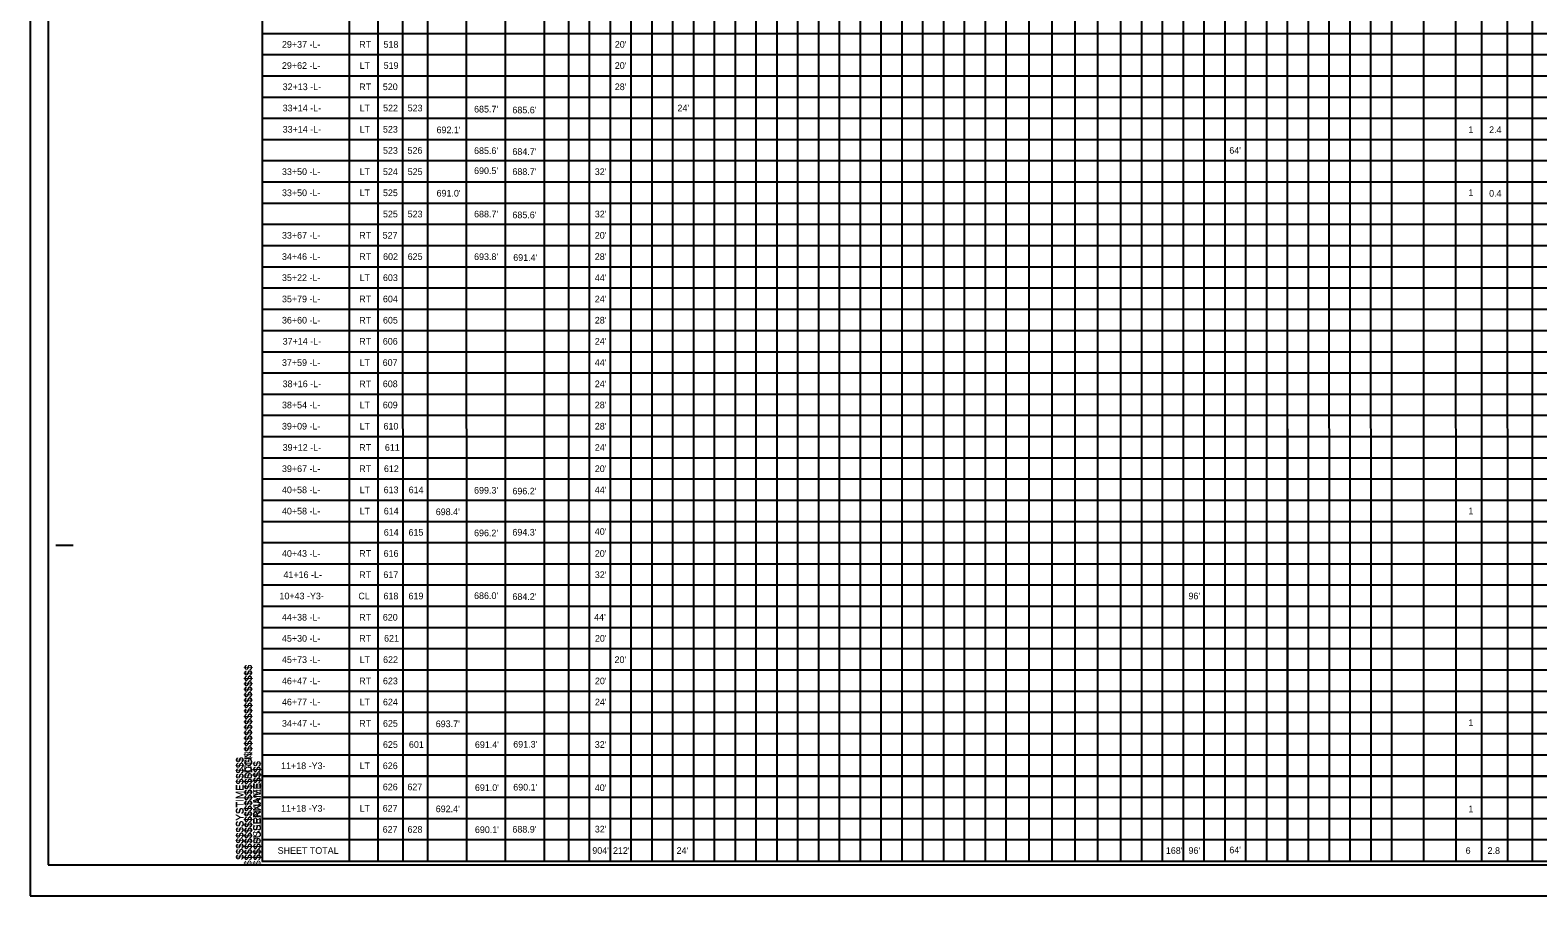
# Model space of a CAD drawing. Extents: x 1912419 to 1914138, y 231793 to 234289.
# Drawn here: x 1912419 to 1913505, y 232988 to 233611 of the extents above; entities that cross this region are included whole.
import ezdxf

# ---------------------------------------------------------------- set-up
doc = ezdxf.new("R2010")
doc.units = 0
for name, color, linetype in [('Sheet Cutting Line CELL', 7, 'Continuous'), ('Sheet Pipe Summary CELL', 7, 'Continuous'), ('Sheet Pipe Summary Grid CELL', 7, 'Continuous'), ('Sheet Plot Border Inside CELL', 7, 'Continuous'), ('Sheet Plot Border Outside CELL', 7, 'Continuous'), ('Sheet Summary Combination CELL', 7, 'Continuous')]:
    doc.layers.add(name, color=color, linetype=linetype)

msp = doc.modelspace()

# ---------------------------------------------------------------- linework, layer by layer
at = {"layer": 'Sheet Cutting Line CELL'}
for p, q in [((1912419.4, 234087.8), (1912419.4, 232987.8)), ((1912419.4, 232987.8), (1914103.4, 232987.8)), ((1912419.4, 232987.8), (1914103.4, 232987.8))]:
    msp.add_line(p, q, dxfattribs=at)
at = {"layer": 'Sheet Pipe Summary CELL'}
for p, q in [((1912437.9, 233240.3), (1912450.4, 233240.3)), ((1912437.9, 233240.3), (1912450.4, 233240.3)), ((1912586.4, 233012.8), (1912586.4, 233012.8))]:
    msp.add_line(p, q, dxfattribs=at)
msp.add_lwpolyline([(1914086.4, 234062.8), (1912586.4, 234062.8), (1912586.4, 233012.8), (1914086.4, 233012.8)], close=True, dxfattribs=at)
at = {"layer": 'Sheet Pipe Summary Grid CELL'}
for p, q in [((1912649.4, 233012.8), (1912649.4, 233966.6)), ((1912670, 233012.8), (1912669.9, 233966.6)), ((1912705.7, 233012.8), (1912705.7, 233966.6)), ((1912733.7, 233012.8), (1912733.6, 233966.6)), ((1912761.7, 233012.8), (1912761.6, 233966.6)), ((1912789.6, 233012.8), (1912789.6, 233966.6)), ((1912807.1, 233012.8), (1912807.1, 233966.6)), ((1912987.1, 233012.8), (1912987.1, 233966.6)), ((1913092.1, 233012.8), (1913092.1, 233966.6)), ((1913204.7, 233012.9), (1913204.6, 233966.7)), ((1913324.7, 233012.9), (1913324.6, 233966.7)), ((1913339.7, 233012.9), (1913339.6, 233966.7)), ((1913354.7, 233012.9), (1913354.6, 233966.7)), ((1913369.7, 233012.9), (1913369.6, 233966.7)), ((1913384.7, 233012.9), (1913384.6, 233966.7)), ((1913399.7, 233012.9), (1913399.6, 233966.7)), ((1913399.6, 233012.9), (1913399.6, 233966.7)), ((1913445.9, 233012.9), (1913445.8, 233966.7)), ((1913500.9, 233012.9), (1913500.8, 233966.7)), ((1913500.9, 233012.9), (1913500.8, 233966.7)), ((1913464.5, 233012.9), (1913464.4, 233876)), ((1912822.1, 233012.8), (1912822.1, 233858.8)), ((1912837.1, 233012.8), (1912837.1, 233858.8)), ((1912852.1, 233012.8), (1912852.1, 233858.8)), ((1912867.1, 233012.8), (1912867.1, 233858.8)), ((1912882.1, 233012.8), (1912882.1, 233858.8)), ((1912897.1, 233012.8), (1912897.1, 233858.8)), ((1912912.1, 233012.8), (1912912.1, 233858.8)), ((1912927.1, 233012.8), (1912927.1, 233858.8)), ((1912942.1, 233012.8), (1912942.1, 233858.8)), ((1912957.1, 233012.8), (1912957.1, 233858.8)), ((1912972.1, 233012.8), (1912972.1, 233858.8)), ((1913002.1, 233012.8), (1913002.1, 233858.8)), ((1913017.1, 233012.8), (1913017.1, 233858.8)), ((1913032.1, 233012.8), (1913032.1, 233858.8)), ((1913047.1, 233012.8), (1913047.1, 233858.8)), ((1913062.1, 233012.8), (1913062.1, 233858.8)), ((1913077.1, 233012.8), (1913077.1, 233858.8)), ((1913092.1, 233012.8), (1913092.1, 233858.8)), ((1913107.1, 233012.8), (1913107.1, 233858.8)), ((1913122.1, 233012.8), (1913122.1, 233858.8)), ((1913138.6, 233012.8), (1913138.6, 233858.8)), ((1913155.1, 233012.8), (1913155.1, 233858.8)), ((1913171.6, 233012.8), (1913171.6, 233858.8)), ((1913188.1, 233012.8), (1913188.1, 233858.8)), ((1913204.6, 233012.8), (1913204.6, 233858.8)), ((1913219.6, 233012.8), (1913219.6, 233858.8)), ((1913234.6, 233012.8), (1913234.6, 233858.8)), ((1913249.6, 233012.8), (1913249.6, 233858.8)), ((1913264.6, 233012.8), (1913264.6, 233858.8)), ((1913279.6, 233012.8), (1913279.6, 233858.8)), ((1913294.6, 233012.8), (1913294.6, 233858.8)), ((1913309.6, 233012.8), (1913309.6, 233858.8)), ((1913324.6, 233012.8), (1913324.6, 233858.8)), ((1913483.1, 233012.9), (1913483, 233852.8)), ((1912687.9, 233012.8), (1912687.8, 233833.3)), ((1912987.1, 233012.8), (1912987.1, 233833.4)), ((1913422.8, 233012.9), (1913422.7, 233833.5)), ((1914086.4, 233608.3), (1912586.4, 233608.3)), ((1914086.4, 233593), (1912586.4, 233593)), ((1914086.4, 233577.8), (1912586.4, 233577.8)), ((1914086.4, 233562.5), (1912586.4, 233562.5)), ((1914086.4, 233547.2), (1912586.4, 233547.2)), ((1914086.4, 233531.9), (1912586.4, 233531.9)), ((1914086.4, 233516.7), (1912586.4, 233516.7)), ((1914086.4, 233501.4), (1912586.4, 233501.4)), ((1914086.4, 233486.1), (1912586.4, 233486.1)), ((1914086.4, 233470.9), (1912586.4, 233470.9)), ((1914086.4, 233455.6), (1912586.4, 233455.6)), ((1914086.4, 233440.3), (1912586.4, 233440.3)), ((1914086.4, 233425.1), (1912586.4, 233425.1)), ((1914086.4, 233409.8), (1912586.4, 233409.8)), ((1914086.4, 233394.5), (1912586.4, 233394.5)), ((1914086.4, 233379.2), (1912586.4, 233379.2)), ((1914086.4, 233364), (1912586.4, 233364)), ((1914086.4, 233348.7), (1912586.4, 233348.7)), ((1914086.4, 233333.4), (1912586.4, 233333.4)), ((1914086.4, 233318.2), (1912586.4, 233318.2)), ((1914086.4, 233302.9), (1912586.4, 233302.9)), ((1914086.4, 233287.6), (1912586.4, 233287.6)), ((1914086.4, 233272.4), (1912586.4, 233272.4)), ((1914086.4, 233257.1), (1912586.4, 233257.1)), ((1914086.4, 233241.8), (1912586.4, 233241.8)), ((1914086.4, 233226.5), (1912586.4, 233226.5)), ((1914086.4, 233211.3), (1912586.4, 233211.3)), ((1914086.4, 233196), (1912586.4, 233196)), ((1914086.4, 233180.7), (1912586.4, 233180.7)), ((1914086.4, 233165.5), (1912586.4, 233165.5)), ((1914086.4, 233150.2), (1912586.4, 233150.2)), ((1914086.4, 233134.9), (1912586.4, 233134.9)), ((1914086.4, 233119.7), (1912586.4, 233119.7)), ((1914086.4, 233104.4), (1912586.4, 233104.4)), ((1914086.4, 233089.1), (1912586.4, 233089.1)), ((1914086.4, 233073.9), (1912586.4, 233073.9)), ((1914086.4, 233073.8), (1912586.4, 233073.8)), ((1914086.4, 233058.6), (1912586.4, 233058.6)), ((1914086.4, 233043.3), (1912586.4, 233043.3)), ((1914086.4, 233028.1), (1912586.4, 233028.1))]:
    msp.add_line(p, q, dxfattribs=at)
at = {"layer": 'Sheet Plot Border Inside CELL'}
msp.add_lwpolyline([(1912432.4, 233010.2), (1914098.9, 233010.2), (1914098.9, 234065.3), (1912432.4, 234065.3)], close=True, dxfattribs=at)
at = {"layer": 'Sheet Plot Border Outside CELL'}
msp.add_lwpolyline([(1912419.4, 232987.8), (1914103.4, 232987.8), (1914103.4, 234087.8), (1912419.4, 234087.8)], close=True, dxfattribs=at)

# ---------------------------------------------------------------- texts
at = {"layer": 'Sheet Pipe Summary CELL'}
for s, p in [('$$$$$$$$$$$$$$$$DGN$$$$$$$$$$$$$$$$', (1912578.8, 233013.6)), ('$$$$$$$$$$$$$$$$DGN$$$$$$$$$$$$$$$$', (1912579.3, 233013.6)), ('$$$$$$SYSTIME$$$$$', (1912572.7, 233013.8)), ('$$$$$$SYSTIME$$$$$', (1912573.2, 233013.8)), ('$$$$USERNAME$$$$', (1912585.1, 233013.7)), ('$$$$USERNAME$$$$', (1912585.6, 233013.7))]:
    msp.add_text(s, height=5.25, rotation=90, dxfattribs=at).set_placement(p)
at = {"layer": 'Sheet Summary Combination CELL'}
for s, p in [('29+37 -L-', (1912600.7, 233598.2)), ('RT', (1912656.3, 233598.2)), ('518', (1912673.8, 233598.2)), ("20'", (1912840.3, 233598.2)), ('29+62 -L-', (1912600.7, 233583)), ('LT', (1912656.6, 233583)), ('519', (1912673.9, 233583)), ("20'", (1912840.3, 233583)), ('32+13 -L-', (1912601.2, 233567.7)), ('RT', (1912656.3, 233567.7)), ('520', (1912673.3, 233567.7)), ("28'", (1912840.3, 233567.7)), ('33+14 -L-', (1912601.2, 233552.4)), ('LT', (1912656.6, 233552.4)), ('522', (1912673.5, 233552.4)), ('523', (1912691.2, 233552.4)), ("685.7'", (1912739, 233551.6)), ("685.6'", (1912766.6, 233551)), ("24'", (1912885.4, 233552.4)), ('33+14 -L-', (1912601.2, 233537.1)), ('LT', (1912656.6, 233537.1)), ('523', (1912673.4, 233537.1)), ("692.1'", (1912712, 233536.7)), ('1', (1913454.8, 233536.8)), ('2.4', (1913469.7, 233536.8)), ('523', (1912673.4, 233521.9)), ('526', (1912691.1, 233521.9)), ("685.6'", (1912739, 233521.7)), ("684.7'", (1912766.6, 233521.1)), ("64'", (1913282.7, 233521.9)), ('33+50 -L-', (1912600.7, 233506.6)), ('LT', (1912656.6, 233506.6)), ('524', (1912673.4, 233506.6)), ('525', (1912691.2, 233506.6)), ("690.5'", (1912739, 233507.3)), ("688.7'", (1912766.6, 233506.7)), ("32'", (1912825.9, 233506.6)), ('33+50 -L-', (1912600.7, 233491.4)), ('LT', (1912656.6, 233491.4)), ('525', (1912673.4, 233491.4)), ("691.0'", (1912712, 233491.1)), ('1', (1913454.8, 233491.5)), ('0.4', (1913469.7, 233491)), ('525', (1912673.4, 233476.1)), ('523', (1912691.2, 233476.1)), ("688.7'", (1912739, 233476.1)), ("685.6'", (1912766.6, 233475.5)), ("32'", (1912825.9, 233476.1)), ('33+67 -L-', (1912600.7, 233460.8)), ('RT', (1912656.3, 233460.8)), ('527', (1912673.2, 233460.8)), ("20'", (1912825.9, 233460.8)), ('34+46 -L-', (1912600.7, 233445.5)), ('RT', (1912656.3, 233445.5)), ('602', (1912673.5, 233445.5)), ('625', (1912691.2, 233445.5)), ("693.8'", (1912739, 233445.4)), ("28'", (1912825.9, 233445.5)), ("691.4'", (1912767.2, 233444.8)), ('35+22 -L-', (1912600.7, 233430.3)), ('LT', (1912656.6, 233430.3)), ('603', (1912673.4, 233430.3)), ("44'", (1912825.9, 233430.3)), ('35+79 -L-', (1912600.7, 233415)), ('RT', (1912656.3, 233415)), ('604', (1912673.4, 233415)), ("24'", (1912825.9, 233415)), ('36+60 -L-', (1912600.7, 233399.7)), ('RT', (1912656.3, 233399.7)), ('605', (1912673.4, 233399.7)), ("28'", (1912825.9, 233399.7)), ('37+14 -L-', (1912601.2, 233384.5)), ('RT', (1912656.3, 233384.5)), ('606', (1912673.3, 233384.5)), ("24'", (1912825.9, 233384.5)), ('37+59 -L-', (1912600.7, 233369.2)), ('LT', (1912656.6, 233369.2)), ('607', (1912673.2, 233369.2)), ("44'", (1912825.9, 233369.2)), ('38+16 -L-', (1912601.2, 233353.9)), ('RT', (1912656.3, 233353.9)), ('608', (1912673.3, 233353.9)), ("24'", (1912825.9, 233353.9)), ('38+54 -L-', (1912600.7, 233338.7)), ('LT', (1912656.6, 233338.7)), ('609', (1912673.3, 233338.7)), ("28'", (1912825.9, 233338.7)), ('39+09 -L-', (1912600.7, 233323.4)), ('LT', (1912656.6, 233323.4)), ('610', (1912673.8, 233323.4)), ("28'", (1912825.9, 233323.4)), ('39+12 -L-', (1912601.2, 233308.1)), ('RT', (1912656.3, 233308.1)), ('611', (1912674.8, 233308.1)), ("24'", (1912825.9, 233308.1)), ('39+67 -L-', (1912600.7, 233292.8)), ('RT', (1912656.3, 233292.8)), ('612', (1912674.1, 233292.8)), ("20'", (1912825.9, 233292.8)), ('40+58 -L-', (1912600.7, 233277.6)), ('LT', (1912656.6, 233277.6)), ('613', (1912673.9, 233277.6)), ('614', (1912691.9, 233277.6)), ("699.3'", (1912739, 233277.3)), ("696.2'", (1912766.6, 233276.7)), ("44'", (1912825.9, 233277.6)), ('40+58 -L-', (1912600.7, 233262.3)), ('LT', (1912656.6, 233262.3)), ('614', (1912674, 233262.3)), ("698.4'", (1912711.4, 233261.8)), ('1', (1913454.8, 233262.4)), ('614', (1912674, 233247)), ('615', (1912691.8, 233247)), ("696.2'", (1912739, 233246.6)), ("694.3'", (1912766.6, 233247.1)), ("40'", (1912825.9, 233247.6)), ('40+43 -L-', (1912600.7, 233231.8)), ('RT', (1912656.3, 233231.8)), ('616', (1912673.9, 233231.8)), ("20'", (1912825.9, 233231.8)), ('41+16 -L-', (1912601.8, 233216.5)), ('RT', (1912656.3, 233216.5)), ('617', (1912673.7, 233216.5)), ("32'", (1912825.9, 233216.5)), ('10+43 -Y3-', (1912598.9, 233201.2)), ('CL', (1912655.7, 233201.2)), ('618', (1912673.8, 233201.2)), ('619', (1912691.8, 233201.2)), ("686.0'", (1912739, 233201.4)), ("684.2'", (1912766.6, 233200.8)), ("96'", (1913253.3, 233201.2)), ('44+38 -L-', (1912600.7, 233185.9)), ('RT', (1912656.3, 233185.9)), ('620', (1912673.3, 233185.9)), ("44'", (1912825.4, 233185.9)), ('45+30 -L-', (1912600.7, 233170.7)), ('RT', (1912656.3, 233170.7)), ('621', (1912674.2, 233170.7)), ("20'", (1912826, 233170.7)), ('45+73 -L-', (1912600.7, 233155.4)), ('LT', (1912656.6, 233155.4)), ('622', (1912673.5, 233155.4)), ("20'", (1912840.1, 233155.4)), ('46+47 -L-', (1912600.7, 233140.1)), ('RT', (1912656.3, 233140.1)), ('623', (1912673.4, 233140.1)), ("20'", (1912826, 233140.1)), ('46+77 -L-', (1912600.7, 233124.9)), ('LT', (1912656.6, 233124.9)), ('624', (1912673.4, 233124.9)), ("24'", (1912826, 233124.9)), ('34+47 -L-', (1912600.7, 233109.5)), ('RT', (1912656.3, 233109.5)), ('625', (1912673.4, 233109.5)), ("693.7'", (1912711.4, 233109.2)), ('1', (1913454.8, 233110)), ('625', (1912673.4, 233094.3)), ('601', (1912692.1, 233094.3)), ("691.4'", (1912739.6, 233094.2)), ("691.3'", (1912767.2, 233094.5)), ("32'", (1912825.9, 233094.3)), ('11+18 -Y3-', (1912600.1, 233079)), ('LT', (1912656.6, 233079)), ('626', (1912673.3, 233079)), ('626', (1912673.3, 233063.8)), ('627', (1912691, 233063.8)), ("691.0'", (1912739.6, 233063.3)), ("690.1'", (1912767.2, 233063.6)), ("40'", (1912825.9, 233063.2)), ('11+18 -Y3-', (1912600.1, 233048.4)), ('LT', (1912656.6, 233048.4)), ('627', (1912673.2, 233048.4)), ("692.4'", (1912711.4, 233048)), ('1', (1913454.8, 233047.9)), ('627', (1912673.2, 233033.2)), ('628', (1912691.1, 233033.2)), ("690.1'", (1912739.6, 233033)), ("688.9'", (1912766.6, 233033.3)), ("32'", (1912825.9, 233033.4)), ('SHEET TOTAL', (1912597.6, 233018)), ("904'", (1912824.1, 233018)), ("212'", (1912839, 233018)), ("24'", (1912884.8, 233018)), ("168'", (1913237, 233018)), ("96'", (1913253.3, 233018)), ("64'", (1913282.7, 233018.4)), ('6', (1913452.8, 233018)), ('2.8', (1913468.6, 233018))]:
    msp.add_text(s, height=4.8, dxfattribs=at).set_placement(p)
for s, p in [('$$$$$$$$$$$$$$$$DGN$$$$$$$$$$$$$$$$', (1912578.8, 233009.4)), ('$$$$USERNAME$$$$', (1912585.3, 233009.4))]:
    msp.add_text(s, height=5.25, rotation=90, dxfattribs=at).set_placement(p)

doc.saveas('drawing.dxf')
